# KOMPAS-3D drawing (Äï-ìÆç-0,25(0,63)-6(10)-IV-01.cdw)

Views: Вид 1, Спереди 2, Проекционный вид 3, Спереди 4, Проекционный вид 5, Проекционный вид 6, Проекционный вид 7, Проекционный вид 8, Проекционный вид 9, Изометрия XYZ 10, Вид 11, Вид 12, Вид 13, Спереди 14, Проекционный вид 15, Проекционный вид 16, Проекционный вид 17, Проекционный вид 18, Проекционный вид 19, Изометрия XYZ 20, Проекционный вид 22, Проекционный вид 23, Проекционный вид 25, Вид 26, Вид 27, Вид 28
Referenced files: GRAPHIC.TDP
Referenced files in Y:\Технический отдел\КБ\Рабочая папка\КД\Тр-ры наружной установки\Тр-ры силовые\ОЛ-НТЗ-6(10)-IV УХЛ1 от 25.10.14\Чертежи\: Трансформатор ОЛ  НТЗ.24.01.00.00.000 ГЧ.cdw
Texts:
  Body Specificaton ( centered )
  Body Specification ( left align )
  Title Specification
  Материал-Предприятие
  Лит-Масса-Масштаб
  Табличка технических
  данных
  ГОСТ 52719-2007
  Маркировка
  Контакт М8
  Ввод кабельный М16
  Крышка
  защитная
  Винт М4х16
  max
  Контакт
  заземления М8
  Защитная крышка условно не показана
  Винт М6
  Шайба A. 6.37 ГОСТ 11371-78
  Шайба
  .Ти9
  ГОСТ
  АД1 ГОСТ 4784-97
  Шайба 6 Л ГОСТ 6402-70
  Шайба пружинная
  Винт А.М 4-6g x 35-22 ГОСТ 1491-80
  Винт обычный
  Винт
  Винт А.М 6-6g x 10 ГОСТ 1491-80
  Шайба210 Л ГОСТ 6402-70
  Болт М10-6g x 10 ГОСТ 7796-70
  Болт
  Шайба A. 10.37 ГОСТ 11371-78
  Поз.
  Кол.
  Приме-
  чание
  Таблица спецификации
  Трансформатор силовой малой мощности
  ОЛ-НТЗ-1,25/6(10)-IV УХЛ1, Т1
  Габаритный чертеж
  М.контр.
  НТЗ
  Михайлов
  Пимурзин
  Морозов
  Бадулин
  Фролова
  НТЗ.24.01.00.00.000
  Без оформления
Dimensions and other numbers on the sheet: 243; 2 шт.; 4 шт.; 306; 220; 14; 4 отв.; 160; 190; 177; 15; 25; 416; 386; 38; 28; 6 шт.; 4; 1; 78; 65Г; 029; 70; -6g; -22; 80; 2; 37; 1:4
